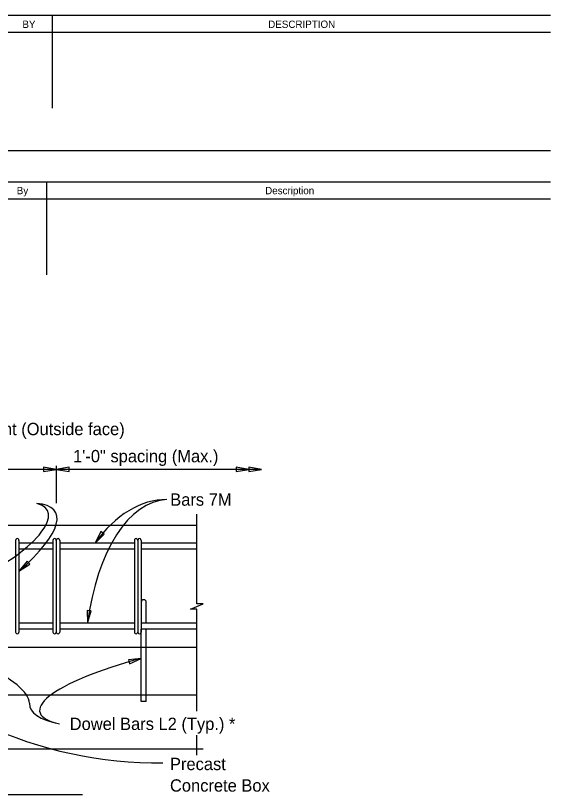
# Model space of a CAD drawing. Extents: x 10691 to 11555, y 76323 to 76455.
# Drawn here: x 10699.88 to 10706.44, y 76408.63 to 76418.19 of the extents above; entities that cross this region are included whole.
import ezdxf

# ---------------------------------------------------------------- set-up
doc = ezdxf.new("R2010")
doc.units = 0
for name, color, linetype in [('AdhocPoint_dp', 7, 'Continuous'), ('Border', 7, 'Continuous'), ('Patterning', 7, 'Continuous'), ('PlotBorder_dp', 7, 'Continuous'), ('TextMisc', 7, 'Continuous')]:
    doc.layers.add(name, color=color, linetype=linetype)

msp = doc.modelspace()

# ---------------------------------------------------------------- linework, layer by layer
at = {"layer": 'AdhocPoint_dp'}
for p, q in [((10699.8802, 76411.7504), (10699.8802, 76410.6255)), ((10699.9219, 76411.7504), (10699.9219, 76410.6255)), ((10700.3385, 76411.7157), (10699.9219, 76411.7157)), ((10700.3385, 76411.7504), (10700.3385, 76410.6255)), ((10700.3802, 76411.7504), (10700.3802, 76410.6255)), ((10700.4219, 76411.7504), (10700.4219, 76410.6255)), ((10701.3385, 76411.7157), (10700.4219, 76411.7157)), ((10701.3385, 76411.7504), (10701.3385, 76410.6255)), ((10701.3802, 76411.7504), (10701.3802, 76410.6255)), ((10701.4219, 76411.7504), (10701.4219, 76410.6255)), ((10702.1067, 76411.7157), (10701.4219, 76411.7157)), ((10700.3385, 76411.6428), (10699.9219, 76411.6428)), ((10701.3385, 76411.6428), (10700.4219, 76411.6428)), ((10702.1067, 76411.6428), (10701.4219, 76411.6428)), ((10701.4845, 76410.733), (10701.4845, 76410.99)), ((10700.3385, 76410.733), (10699.9219, 76410.733)), ((10701.3385, 76410.733), (10700.4219, 76410.733)), ((10702.1067, 76410.733), (10701.4219, 76410.733)), ((10700.3385, 76410.6601), (10699.9219, 76410.6601)), ((10701.3385, 76410.6601), (10700.4219, 76410.6601)), ((10702.1067, 76410.6601), (10701.4219, 76410.6601)), ((10701.422, 76409.7712), (10701.422, 76410.6601)), ((10701.4845, 76409.7712), (10701.4845, 76410.6601)), ((10701.4845, 76409.7712), (10701.422, 76409.7712))]:
    msp.add_line(p, q, dxfattribs=at)
for centre, radius, start, end in [((10699.9011, 76411.7504), 0.0209, 359.99895, 180), ((10700.3594, 76411.7504), 0.0209, 0, 180.00105), ((10700.4011, 76411.7504), 0.0209, 359.99895, 180), ((10701.3594, 76411.7504), 0.0209, 0, 180.00105), ((10701.4011, 76411.7504), 0.0209, 359.99895, 180), ((10701.4532, 76410.99), 0.0312, 0, 180), ((10699.9011, 76410.6255), 0.0209, 180, 0.00105), ((10700.3594, 76410.6255), 0.0209, 179.99895, 0), ((10700.4011, 76410.6255), 0.0209, 180, 0.00105), ((10701.3594, 76410.6255), 0.0209, 179.99895, 0), ((10701.4011, 76410.6255), 0.0209, 180, 0.00105)]:
    msp.add_arc(centre, radius, start, end, dxfattribs=at)
at = {"layer": 'Border'}
for p, q in [((10706.4449, 76418.1912), (10690.9862, 76418.1912)), ((10700.3283, 76418.1912), (10700.3283, 76417.055)), ((10690.9862, 76417.9864), (10706.4449, 76417.9864)), ((10706.4449, 76416.5321), (10690.9857, 76416.5321)), ((10706.4449, 76416.1458), (10690.9857, 76416.1458)), ((10700.2611, 76416.1458), (10700.2611, 76415.0099)), ((10690.9857, 76415.941), (10706.4449, 76415.941))]:
    msp.add_line(p, q, dxfattribs=at)
at = {"layer": 'PlotBorder_dp'}
for p, q in [((10697.3803, 76411.9379), (10702.1067, 76411.9379)), ((10697.3803, 76410.4379), (10702.1067, 76410.4379)), ((10697.3803, 76409.8546), (10702.1067, 76409.8546))]:
    msp.add_line(p, q, dxfattribs=at)
at = {"layer": 'TextMisc'}
for p, q in [((10700.3802, 76412.6213), (10698.3802, 76412.6213)), ((10700.3802, 76412.6646), (10700.3802, 76412.2057)), ((10702.9005, 76412.6213), (10700.3802, 76412.6213)), ((10697.3803, 76408.6323), (10700.7029, 76408.6323))]:
    msp.add_line(p, q, dxfattribs=at)
for points in [[(10700.3802, 76412.6213), (10700.224, 76412.6478), (10700.224, 76412.5948)], [(10700.3802, 76412.6213), (10700.5364, 76412.5948), (10700.5364, 76412.6478)], [(10702.7443, 76412.6213), (10702.5881, 76412.6477), (10702.5881, 76412.5948)], [(10702.9005, 76412.6213), (10702.7443, 76412.6477), (10702.7443, 76412.5948)], [(10700.8558, 76411.7157), (10700.9682, 76411.8273), (10700.9252, 76411.8582)], [(10699.9219, 76411.3743), (10700.057, 76411.4572), (10700.0222, 76411.497)], [(10700.763, 76410.733), (10700.8098, 76410.8843), (10700.7574, 76410.8913)], [(10701.422, 76410.3009), (10701.2643, 76410.2859), (10701.278, 76410.2348)]]:
    msp.add_lwpolyline(points, close=True, dxfattribs=at)
for points in [[(10702.1067, 76409.6525), (10702.1067, 76410.9042), (10702.0292, 76410.9042), (10702.1067, 76410.9379), (10702.1842, 76410.9717), (10702.1067, 76410.9717), (10702.1067, 76412.0731)], [(10692.5765, 76409.1913), (10697.3466, 76409.1913), (10697.3466, 76409.2688), (10697.3803, 76409.1913), (10697.4141, 76409.1138), (10697.4141, 76409.1913), (10702.1842, 76409.1913)], [(10702.1067, 76409.1138), (10702.1067, 76409.3604)]]:
    msp.add_lwpolyline(points, dxfattribs=at)
msp.add_arc((10701.6228, 76414.0809), 5.0601, 245.05406, 270.75532, dxfattribs=at)
for centre, major_axis, ratio, start_param, end_param in [((10701.8349, 76410.028), (0.0978, -2.2237), 0.496339, 3.141593, 4.368084), ((10701.7272, 76409.8876), (-0.0099, -2.3641), 0.584686, 3.141593, 3.830855), ((10698.9917, 76411.5335), (-1.2833, -0.5749), 0.297573, 1.777046, 3.487769), ((10698.2958, 76410.9948), (-2.0758, -1.0972), 0.248993, 2.329341, 3.503084), ((10702.1144, 76410.0194), (1.9375, 0.3723), 0.217631, 1.894137, 3.605568), ((10698.0153, 76410.1109), (-2.0352, 0.3967), 0.256616, 3.21042, 3.957123), ((10702.09, 76410.1109), (2.0352, 0.3967), 0.256616, 3.072765, 3.700054)]:
    msp.add_ellipse(centre, major_axis=major_axis, ratio=ratio, start_param=start_param, end_param=end_param, dxfattribs=at)

# ---------------------------------------------------------------- texts
at = {"layer": 'Patterning'}
for s, height, p in [('BY', 0.09008, (10699.9638, 76418.0394)), ('By', 0.09008, (10699.8947, 76415.9982)), ('1\'-0" spacing (Max.)', 0.1512, (10700.5857, 76412.7088)), ('Dowel Bars L2 (Typ.) *', 0.1512, (10700.5447, 76409.4231))]:
    msp.add_text(s, height=height, dxfattribs=at).set_placement(p)
for s, height, rotation, p in [('DESCRIPTION', 0.090052, 0.04975, (10702.9805, 76418.0391)), ('Description', 0.090052, 0.04975, (10702.9435, 76415.9982)), ('Bars 7M', 0.1512, 360, (10701.7784, 76412.1755)), ('Precast', 0.1512, 360, (10701.7753, 76408.9305)), ('Concrete Box', 0.1512, 360, (10701.7753, 76408.6665))]:
    msp.add_text(s, height=height, rotation=rotation, dxfattribs=at).set_placement(p)
at = {"layer": 'TextMisc'}
msp.add_text('℄ Precast Box Joint (Outside face)', height=0.1512, dxfattribs=at).set_placement((10698.1822, 76413.0415))

doc.saveas('drawing.dxf')
